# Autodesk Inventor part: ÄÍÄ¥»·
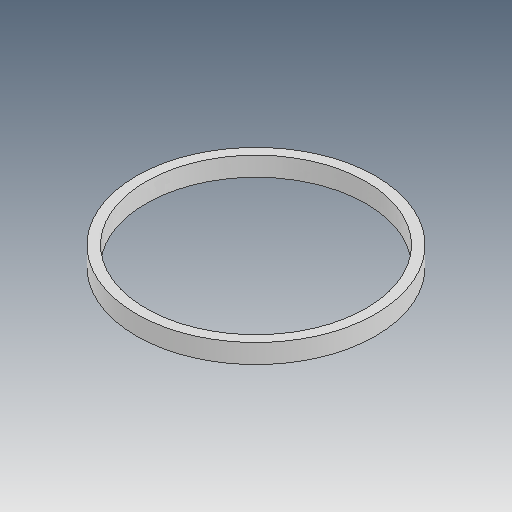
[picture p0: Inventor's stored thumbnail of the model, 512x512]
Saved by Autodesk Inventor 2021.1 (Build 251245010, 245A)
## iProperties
Created: 2013-04
Part Number: ÄÍÄ¥»·
Material: Ogólny
Document SubType Name: Modeling
Designer: user
Density: 1 g/cm^3
Appearance: Domyślna
Author: user
Revision Number: ÈÎºÎ
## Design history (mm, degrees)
feature "Ðý×ª1"
node "Bryła1"
